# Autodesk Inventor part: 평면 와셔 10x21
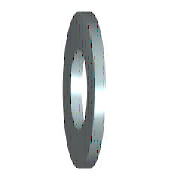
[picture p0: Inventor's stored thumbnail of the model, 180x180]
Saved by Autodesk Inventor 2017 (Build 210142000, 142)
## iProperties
IsCustomPart: 1
Created: 2012-02
Part Number: 평면 와셔 10x21
Material: 강철, 연강
Description: 평면 와셔
Document SubType Name: Modeling
Standard: KS B 1326
Designer: mduedu
Standards Organization: KS
Language: ko-KR
Size Designation: 10x21
Categories: <MemberInstance><Categories><Category DisplayName="조임쇠" InternalName="e4da775c-781d-43d5-af7c-5136215cf5a6" Mnemonic="FSTN"><Category DisplayName="와셔" InternalN
Density: 1 g/cm^3
Appearance: 노란색
Author: mduedu
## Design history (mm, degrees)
sketch "스케치"
  geometry: C1 r 10.5 at (0, 0); C2 r 5.25 at (0, 0); 1 further point
  constraints: 2 centre point, 2 coincident
  dimensions: "d0" = 10.5 diameter of C2 (= SD1); "d1" = 21 diameter of C1 (= SD2)
extrude "본체" new body sketch "스케치" distance "d2" = 2 (= SD); taper "d3" = 0 deg
workaxis "Work Axis1"
workplane "Work Plane1"
body "Solid1"
other parameters: "SD1" = 10.5 [user parameter; used in 1 equation term], "SD2" = 21 [user parameter; used in 1 equation term], "SD" = 2 [user parameter; used in 1 equation term], "d4" = 0, "d5" = 0, "d6" = 0, "d7" = 0
